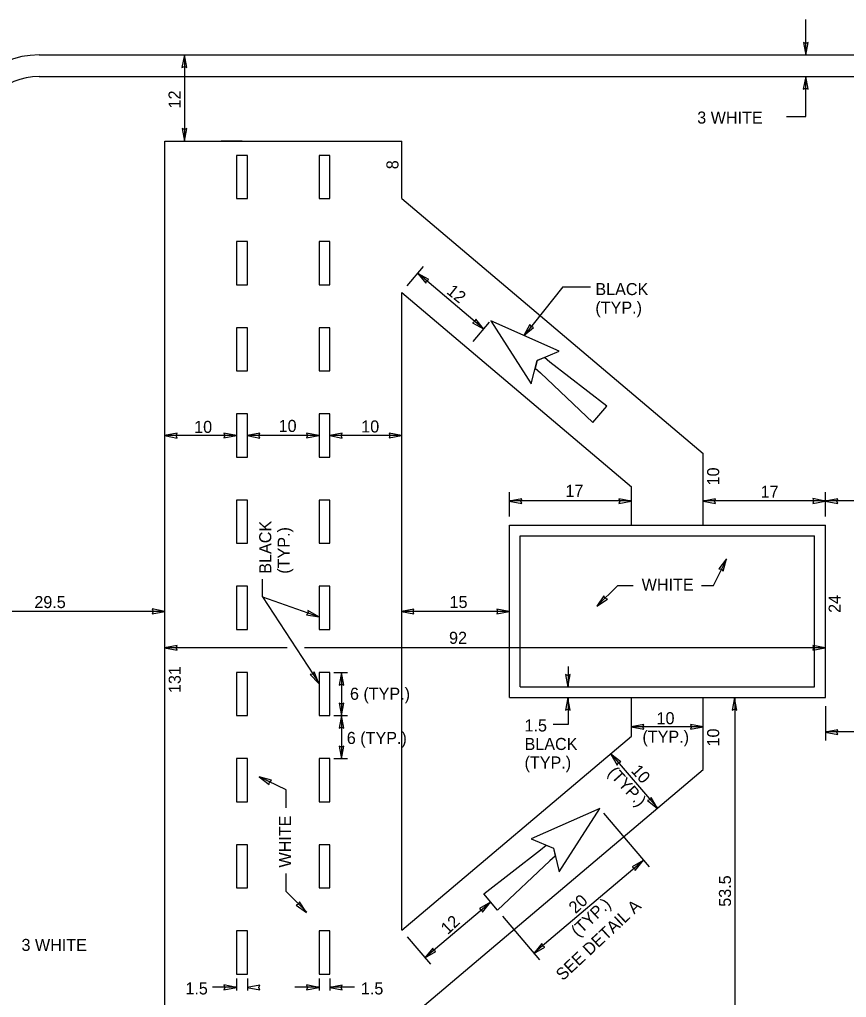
# Model space of a CAD drawing. Extents: x 319706 to 320019, y 1621790 to 1621996.
# Drawn here: x 319813.6 to 319909.6, y 1621877.2 to 1621990.6 of the extents above; entities that cross this region are included whole.
import ezdxf

# ---------------------------------------------------------------- set-up
doc = ezdxf.new("R2010")
doc.units = 0
for name, color, linetype in [('1', 7, 'Continuous'), ('40', 7, 'Continuous'), ('48', 7, 'Continuous'), ('52', 7, 'Continuous')]:
    doc.layers.add(name, color=color, linetype=linetype)

msp = doc.modelspace()

# ---------------------------------------------------------------- linework, layer by layer
at = {"layer": '1'}
for p, q in [((319815.88, 1621986.54), (319975.88, 1621986.54)), ((319815.88, 1621984.04), (319975.88, 1621984.04)), ((319830.47, 1621976.54), (319857.96, 1621976.54)), ((319830.47, 1621867.37), (319830.47, 1621976.54)), ((319857.96, 1621969.87), (319857.96, 1621976.54)), ((319857.96, 1621969.87), (319892.96, 1621940.29)), ((319857.96, 1621958.96), (319884.63, 1621936.42)), ((319857.96, 1621884.95), (319857.96, 1621958.96)), ((319892.96, 1621931.96), (319892.96, 1621940.29)), ((319884.63, 1621931.96), (319884.63, 1621936.42)), ((319870.46, 1621931.96), (319907.13, 1621931.96)), ((319870.46, 1621911.96), (319870.46, 1621931.96)), ((319907.13, 1621911.96), (319907.13, 1621931.96)), ((319871.71, 1621930.71), (319905.88, 1621930.71)), ((319871.71, 1621913.21), (319871.71, 1621930.71)), ((319905.88, 1621913.21), (319905.88, 1621930.71)), ((319871.71, 1621913.21), (319905.88, 1621913.21)), ((319870.46, 1621911.96), (319907.13, 1621911.96)), ((319884.63, 1621907.49), (319884.63, 1621911.96)), ((319892.96, 1621903.62), (319892.96, 1621911.96)), ((319857.96, 1621884.95), (319884.63, 1621907.49)), ((319857.96, 1621874.04), (319892.96, 1621903.62))]:
    msp.add_line(p, q, dxfattribs=at)
for radius in [10, 7.5]:
    msp.add_arc((319815.88, 1621976.54), radius, 90, 180, dxfattribs=at)
at = {"layer": '40'}
for p, q in [((319840.05, 1621974.87), (319838.8, 1621974.87)), ((319838.8, 1621974.87), (319838.8, 1621969.87)), ((319840.05, 1621969.87), (319840.05, 1621974.87)), ((319849.63, 1621974.87), (319848.38, 1621974.87)), ((319848.38, 1621974.87), (319848.38, 1621969.87)), ((319849.63, 1621969.87), (319849.63, 1621974.87)), ((319838.8, 1621969.87), (319840.05, 1621969.87)), ((319848.38, 1621969.87), (319849.63, 1621969.87)), ((319840.05, 1621964.87), (319838.8, 1621964.87)), ((319838.8, 1621964.87), (319838.8, 1621959.87)), ((319840.05, 1621959.87), (319840.05, 1621964.87)), ((319849.63, 1621964.87), (319848.38, 1621964.87)), ((319848.38, 1621964.87), (319848.38, 1621959.87)), ((319849.63, 1621959.87), (319849.63, 1621964.87)), ((319838.8, 1621959.87), (319840.05, 1621959.87)), ((319848.38, 1621959.87), (319849.63, 1621959.87)), ((319868.29, 1621955.69), (319872.99, 1621948.37)), ((319876.24, 1621952.17), (319868.29, 1621955.69)), ((319840.05, 1621954.87), (319838.8, 1621954.87)), ((319838.8, 1621954.87), (319838.8, 1621949.87)), ((319840.05, 1621949.87), (319840.05, 1621954.87)), ((319849.63, 1621954.87), (319848.38, 1621954.87)), ((319848.38, 1621954.87), (319848.38, 1621949.87)), ((319849.63, 1621949.87), (319849.63, 1621954.87)), ((319873.67, 1621951.08), (319876.24, 1621952.17)), ((319872.99, 1621948.37), (319873.67, 1621951.08)), ((319873.67, 1621951.08), (319873.44, 1621950.18)), ((319874.53, 1621951.44), (319873.67, 1621951.08)), ((319875.16, 1621950.9), (319874.53, 1621951.44)), ((319881.76, 1621945.79), (319875.16, 1621950.9)), ((319838.8, 1621949.87), (319840.05, 1621949.87)), ((319848.38, 1621949.87), (319849.63, 1621949.87)), ((319873.44, 1621950.18), (319874.07, 1621949.63)), ((319874.07, 1621949.63), (319880.13, 1621943.89)), ((319840.05, 1621944.87), (319838.8, 1621944.87)), ((319838.8, 1621944.87), (319838.8, 1621939.87)), ((319840.05, 1621939.87), (319840.05, 1621944.87)), ((319849.63, 1621944.87), (319848.38, 1621944.87)), ((319848.38, 1621944.87), (319848.38, 1621939.87)), ((319849.63, 1621939.87), (319849.63, 1621944.87)), ((319880.13, 1621943.89), (319881.76, 1621945.79)), ((319838.8, 1621939.87), (319840.05, 1621939.87)), ((319848.38, 1621939.87), (319849.63, 1621939.87)), ((319840.05, 1621934.87), (319838.8, 1621934.87)), ((319838.8, 1621934.87), (319838.8, 1621929.87)), ((319840.05, 1621929.87), (319840.05, 1621934.87)), ((319849.63, 1621934.87), (319848.38, 1621934.87)), ((319848.38, 1621934.87), (319848.38, 1621929.87)), ((319849.63, 1621929.87), (319849.63, 1621934.87)), ((319838.8, 1621929.87), (319840.05, 1621929.87)), ((319848.38, 1621929.87), (319849.63, 1621929.87)), ((319840.05, 1621924.87), (319838.8, 1621924.87)), ((319838.8, 1621924.87), (319838.8, 1621919.87)), ((319840.05, 1621919.87), (319840.05, 1621924.87)), ((319849.63, 1621924.87), (319848.38, 1621924.87)), ((319848.38, 1621924.87), (319848.38, 1621919.87)), ((319849.63, 1621919.87), (319849.63, 1621924.87)), ((319838.8, 1621919.87), (319840.05, 1621919.87)), ((319848.38, 1621919.87), (319849.63, 1621919.87)), ((319840.05, 1621914.87), (319838.8, 1621914.87)), ((319838.8, 1621914.87), (319838.8, 1621909.87)), ((319840.05, 1621909.87), (319840.05, 1621914.87)), ((319849.63, 1621914.87), (319848.38, 1621914.87)), ((319848.38, 1621914.87), (319848.38, 1621909.87)), ((319849.63, 1621909.87), (319849.63, 1621914.87)), ((319838.8, 1621909.87), (319840.05, 1621909.87)), ((319848.38, 1621909.87), (319849.63, 1621909.87)), ((319840.05, 1621904.87), (319838.8, 1621904.87)), ((319838.8, 1621904.87), (319838.8, 1621899.87)), ((319840.05, 1621899.87), (319840.05, 1621904.87)), ((319849.63, 1621904.87), (319848.38, 1621904.87)), ((319848.38, 1621904.87), (319848.38, 1621899.87)), ((319849.63, 1621899.87), (319849.63, 1621904.87)), ((319838.8, 1621899.87), (319840.05, 1621899.87)), ((319848.38, 1621899.87), (319849.63, 1621899.87)), ((319880.94, 1621899.07), (319872.99, 1621895.55)), ((319876.24, 1621891.75), (319880.94, 1621899.07)), ((319840.05, 1621894.87), (319838.8, 1621894.87)), ((319838.8, 1621894.87), (319838.8, 1621889.87)), ((319840.05, 1621889.87), (319840.05, 1621894.87)), ((319849.63, 1621894.87), (319848.38, 1621894.87)), ((319848.38, 1621894.87), (319848.38, 1621889.87)), ((319849.63, 1621889.87), (319849.63, 1621894.87)), ((319872.99, 1621895.55), (319875.57, 1621894.46)), ((319867.48, 1621889.17), (319874.07, 1621894.28)), ((319874.07, 1621894.28), (319874.71, 1621894.82)), ((319874.71, 1621894.82), (319875.57, 1621894.46)), ((319875.57, 1621894.46), (319875.79, 1621893.56)), ((319875.57, 1621894.46), (319876.24, 1621891.75)), ((319875.16, 1621893.02), (319869.1, 1621887.28)), ((319875.79, 1621893.56), (319875.16, 1621893.02)), ((319838.8, 1621889.87), (319840.05, 1621889.87)), ((319848.38, 1621889.87), (319849.63, 1621889.87)), ((319869.1, 1621887.28), (319867.48, 1621889.17)), ((319840.05, 1621884.87), (319838.8, 1621884.87)), ((319838.8, 1621884.87), (319838.8, 1621879.87)), ((319840.05, 1621879.87), (319840.05, 1621884.87)), ((319849.63, 1621884.87), (319848.38, 1621884.87)), ((319848.38, 1621884.87), (319848.38, 1621879.87)), ((319849.63, 1621879.87), (319849.63, 1621884.87)), ((319838.8, 1621879.87), (319840.05, 1621879.87)), ((319848.38, 1621879.87), (319849.63, 1621879.87))]:
    msp.add_line(p, q, dxfattribs=at)
at = {"layer": '48'}
for p, q in [((319904.87, 1621986.54), (319904.87, 1621990.64)), ((319832.74, 1621986.54), (319832.74, 1621976.54)), ((319904.87, 1621979.38), (319904.87, 1621984.04)), ((319902.62, 1621979.38), (319904.87, 1621979.38)), ((319839.43, 1621976.54), (319837.02, 1621976.54)), ((319858.61, 1621959.73), (319860.5, 1621961.97)), ((319859.86, 1621961.21), (319867.5, 1621954.75)), ((319876.65, 1621959.64), (319872.16, 1621953.98)), ((319876.65, 1621959.64), (319879.86, 1621959.64)), ((319866.25, 1621953.27), (319868.14, 1621955.52)), ((319838.8, 1621942.37), (319830.47, 1621942.37)), ((319848.38, 1621942.37), (319840.05, 1621942.37)), ((319857.96, 1621942.37), (319849.63, 1621942.37)), ((319870.46, 1621932.97), (319870.46, 1621935.78)), ((319907.13, 1621932.97), (319907.13, 1621935.78)), ((319884.63, 1621934.78), (319870.46, 1621934.78)), ((319907.13, 1621934.78), (319892.96, 1621934.78)), ((319919.63, 1621934.78), (319907.13, 1621934.78)), ((319894.16, 1621924.96), (319895.7, 1621928.07)), ((319841.8, 1621923.64), (319841.8, 1621925.71)), ((319883.04, 1621924.96), (319880.62, 1621922.57)), ((319883.04, 1621924.96), (319884.83, 1621924.96)), ((319892.74, 1621924.96), (319894.16, 1621924.96)), ((319841.8, 1621923.64), (319848.38, 1621921.33)), ((319841.8, 1621923.64), (319848.38, 1621913.58)), ((319830.47, 1621921.96), (319805.88, 1621921.96)), ((319870.46, 1621921.96), (319857.96, 1621921.96)), ((319844.66, 1621917.74), (319830.47, 1621917.74)), ((319907.13, 1621917.74), (319846.69, 1621917.74)), ((319877.27, 1621915.58), (319877.27, 1621913.21)), ((319850.09, 1621914.87), (319851.66, 1621914.87)), ((319850.99, 1621914.87), (319850.99, 1621909.87)), ((319877.27, 1621911.96), (319877.27, 1621908.84)), ((319896.62, 1621911.96), (319896.62, 1621867.37)), ((319907.13, 1621910.96), (319907.13, 1621906.98)), ((319850.09, 1621909.87), (319851.66, 1621909.87)), ((319850.99, 1621909.87), (319850.99, 1621904.87)), ((319877.27, 1621908.84), (319875.54, 1621908.84)), ((319884.63, 1621908.59), (319892.96, 1621908.59)), ((319919.63, 1621907.98), (319907.13, 1621907.98)), ((319882.25, 1621905.42), (319887.67, 1621899.09)), ((319850.09, 1621904.87), (319851.66, 1621904.87)), ((319844.55, 1621901.23), (319841.44, 1621902.77)), ((319844.55, 1621899.16), (319844.55, 1621901.23)), ((319881.4, 1621898.53), (319886.67, 1621892.3)), ((319886.03, 1621893.06), (319873.31, 1621882.29)), ((319844.55, 1621889.46), (319844.55, 1621891.53)), ((319844.55, 1621889.46), (319846.95, 1621887.04)), ((319868.29, 1621888.23), (319860.66, 1621881.76)), ((319869.68, 1621886.58), (319873.95, 1621881.52)), ((319858.61, 1621884.19), (319861.3, 1621881)), ((319838.8, 1621879.37), (319838.8, 1621877.96)), ((319840.05, 1621879.37), (319840.05, 1621877.96)), ((319848.38, 1621879.37), (319848.38, 1621877.96)), ((319849.63, 1621879.37), (319849.63, 1621877.96)), ((319838.8, 1621878.33), (319835.99, 1621878.33)), ((319848.38, 1621878.33), (319845.57, 1621878.33)), ((319852.5, 1621878.33), (319849.63, 1621878.33))]:
    msp.add_line(p, q, dxfattribs=at)
at = {"layer": '52'}
for p, q in [((319904.85, 1621987.86), (319904.58, 1621987.97)), ((319904.58, 1621987.97), (319904.85, 1621986.52)), ((319904.85, 1621986.52), (319905.13, 1621987.97)), ((319905.13, 1621987.97), (319904.85, 1621987.86)), ((319832.74, 1621986.54), (319832.46, 1621985.09)), ((319833.01, 1621985.09), (319832.74, 1621986.54)), ((319832.46, 1621985.09), (319832.74, 1621985.2)), ((319832.74, 1621985.2), (319833.01, 1621985.09)), ((319904.85, 1621984.02), (319904.57, 1621982.57)), ((319905.12, 1621982.57), (319904.85, 1621984.02)), ((319904.57, 1621982.57), (319904.85, 1621982.68)), ((319904.85, 1621982.68), (319905.12, 1621982.57)), ((319832.74, 1621977.88), (319832.47, 1621977.99)), ((319832.47, 1621977.99), (319832.74, 1621976.54)), ((319832.74, 1621976.54), (319833.02, 1621977.99)), ((319833.02, 1621977.99), (319832.74, 1621977.88)), ((319859.84, 1621961.19), (319860.76, 1621960.04)), ((319861.12, 1621960.46), (319859.84, 1621961.19)), ((319860.76, 1621960.04), (319860.86, 1621960.32)), ((319860.86, 1621960.32), (319861.12, 1621960.46)), ((319866.45, 1621955.6), (319866.19, 1621955.46)), ((319866.19, 1621955.46), (319867.47, 1621954.73)), ((319866.55, 1621955.88), (319866.45, 1621955.6)), ((319867.47, 1621954.73), (319866.55, 1621955.88)), ((319872.82, 1621955.26), (319872.14, 1621953.96)), ((319872.97, 1621955.01), (319872.82, 1621955.26)), ((319873.26, 1621954.92), (319872.97, 1621955.01)), ((319872.14, 1621953.96), (319873.26, 1621954.92)), ((319831.9, 1621942.63), (319830.45, 1621942.36)), ((319831.79, 1621942.36), (319831.9, 1621942.63)), ((319838.78, 1621942.36), (319837.33, 1621942.64)), ((319837.33, 1621942.64), (319837.44, 1621942.36)), ((319841.48, 1621942.63), (319840.03, 1621942.36)), ((319841.37, 1621942.36), (319841.48, 1621942.63)), ((319848.36, 1621942.36), (319846.91, 1621942.64)), ((319846.91, 1621942.64), (319847.02, 1621942.36)), ((319851.06, 1621942.63), (319849.61, 1621942.36)), ((319850.95, 1621942.36), (319851.06, 1621942.63)), ((319857.94, 1621942.36), (319856.49, 1621942.64)), ((319856.49, 1621942.64), (319856.6, 1621942.36)), ((319830.45, 1621942.36), (319831.9, 1621942.08)), ((319831.9, 1621942.08), (319831.79, 1621942.36)), ((319837.44, 1621942.36), (319837.33, 1621942.09)), ((319837.33, 1621942.09), (319838.78, 1621942.36)), ((319840.03, 1621942.36), (319841.48, 1621942.08)), ((319841.48, 1621942.08), (319841.37, 1621942.36)), ((319847.02, 1621942.36), (319846.91, 1621942.09)), ((319846.91, 1621942.09), (319848.36, 1621942.36)), ((319849.61, 1621942.36), (319851.06, 1621942.08)), ((319851.06, 1621942.08), (319850.95, 1621942.36)), ((319856.6, 1621942.36), (319856.49, 1621942.09)), ((319856.49, 1621942.09), (319857.94, 1621942.36)), ((319871.89, 1621935.03), (319870.44, 1621934.76)), ((319870.44, 1621934.76), (319871.89, 1621934.48)), ((319871.78, 1621934.76), (319871.89, 1621935.03)), ((319871.89, 1621934.48), (319871.78, 1621934.76)), ((319884.61, 1621934.75), (319883.16, 1621935.03)), ((319883.16, 1621935.03), (319883.27, 1621934.75)), ((319883.27, 1621934.75), (319883.16, 1621934.48)), ((319883.16, 1621934.48), (319884.61, 1621934.75)), ((319894.39, 1621935.02), (319892.94, 1621934.75)), ((319892.94, 1621934.75), (319894.39, 1621934.47)), ((319894.28, 1621934.75), (319894.39, 1621935.02)), ((319894.39, 1621934.47), (319894.28, 1621934.75)), ((319907.11, 1621934.76), (319905.66, 1621935.04)), ((319905.66, 1621935.04), (319905.77, 1621934.76)), ((319905.77, 1621934.76), (319905.66, 1621934.49)), ((319905.66, 1621934.49), (319907.11, 1621934.76)), ((319908.56, 1621935.03), (319907.11, 1621934.76)), ((319907.11, 1621934.76), (319908.56, 1621934.48)), ((319908.45, 1621934.76), (319908.56, 1621935.03)), ((319908.56, 1621934.48), (319908.45, 1621934.76)), ((319895.67, 1621928.05), (319894.77, 1621926.88)), ((319895.27, 1621926.64), (319895.67, 1621928.05)), ((319894.77, 1621926.88), (319895.07, 1621926.85)), ((319895.07, 1621926.85), (319895.27, 1621926.64)), ((319881.44, 1621923.77), (319880.6, 1621922.55)), ((319880.6, 1621922.55), (319881.83, 1621923.37)), ((319881.55, 1621923.5), (319881.44, 1621923.77)), ((319881.83, 1621923.37), (319881.55, 1621923.5)), ((319830.47, 1621921.96), (319829.02, 1621922.24)), ((319829.02, 1621922.24), (319829.13, 1621921.96)), ((319859.39, 1621922.21), (319857.94, 1621921.94)), ((319859.28, 1621921.94), (319859.39, 1621922.21)), ((319870.44, 1621921.93), (319868.99, 1621922.21)), ((319868.99, 1621922.21), (319869.1, 1621921.93)), ((319829.13, 1621921.96), (319829.02, 1621921.69)), ((319829.02, 1621921.69), (319830.47, 1621921.96)), ((319847.09, 1621921.76), (319846.9, 1621921.54)), ((319846.9, 1621921.54), (319848.36, 1621921.32)), ((319848.36, 1621921.32), (319847.08, 1621922.06)), ((319847.08, 1621922.06), (319847.09, 1621921.76)), ((319857.94, 1621921.94), (319859.39, 1621921.66)), ((319859.39, 1621921.66), (319859.28, 1621921.94)), ((319869.1, 1621921.93), (319868.99, 1621921.66)), ((319868.99, 1621921.66), (319870.44, 1621921.93)), ((319831.9, 1621918), (319830.45, 1621917.73)), ((319830.45, 1621917.73), (319831.9, 1621917.45)), ((319831.79, 1621917.73), (319831.9, 1621918)), ((319831.9, 1621917.45), (319831.79, 1621917.73)), ((319907.11, 1621917.72), (319905.66, 1621918)), ((319905.66, 1621918), (319905.77, 1621917.72)), ((319905.77, 1621917.72), (319905.66, 1621917.45)), ((319905.66, 1621917.45), (319907.11, 1621917.72)), ((319847.63, 1621914.69), (319847.34, 1621914.64)), ((319847.34, 1621914.64), (319848.36, 1621913.57)), ((319847.8, 1621914.94), (319847.63, 1621914.69)), ((319848.36, 1621913.57), (319847.8, 1621914.94)), ((319850.98, 1621914.86), (319850.7, 1621913.41)), ((319851.25, 1621913.41), (319850.98, 1621914.86)), ((319877.25, 1621914.52), (319876.98, 1621914.63)), ((319876.98, 1621914.63), (319877.25, 1621913.18)), ((319877.25, 1621913.18), (319877.53, 1621914.63)), ((319877.53, 1621914.63), (319877.25, 1621914.52)), ((319850.7, 1621913.41), (319850.98, 1621913.52)), ((319850.98, 1621913.52), (319851.25, 1621913.41)), ((319877.25, 1621911.94), (319876.97, 1621910.49)), ((319877.52, 1621910.49), (319877.25, 1621911.94)), ((319896.59, 1621911.94), (319896.31, 1621910.49)), ((319896.86, 1621910.49), (319896.59, 1621911.94)), ((319850.98, 1621911.2), (319850.71, 1621911.31)), ((319850.71, 1621911.31), (319850.98, 1621909.86)), ((319850.98, 1621909.86), (319851.26, 1621911.31)), ((319851.26, 1621911.31), (319850.98, 1621911.2)), ((319850.98, 1621909.86), (319850.7, 1621908.41)), ((319851.25, 1621908.41), (319850.98, 1621909.86)), ((319876.97, 1621910.49), (319877.25, 1621910.6)), ((319877.25, 1621910.6), (319877.52, 1621910.49)), ((319896.31, 1621910.49), (319896.59, 1621910.6)), ((319896.59, 1621910.6), (319896.86, 1621910.49)), ((319850.7, 1621908.41), (319850.98, 1621908.52)), ((319850.98, 1621908.52), (319851.25, 1621908.41)), ((319886.06, 1621908.84), (319884.61, 1621908.57)), ((319884.61, 1621908.57), (319886.06, 1621908.29)), ((319885.95, 1621908.57), (319886.06, 1621908.84)), ((319886.06, 1621908.29), (319885.95, 1621908.57)), ((319892.94, 1621908.57), (319891.49, 1621908.85)), ((319891.49, 1621908.85), (319891.6, 1621908.57)), ((319891.6, 1621908.57), (319891.49, 1621908.3)), ((319891.49, 1621908.3), (319892.94, 1621908.57)), ((319908.56, 1621908.22), (319907.11, 1621907.95)), ((319907.11, 1621907.95), (319908.56, 1621907.67)), ((319908.45, 1621907.95), (319908.56, 1621908.22)), ((319908.56, 1621907.67), (319908.45, 1621907.95)), ((319850.98, 1621906.2), (319850.71, 1621906.31)), ((319850.71, 1621906.31), (319850.98, 1621904.86)), ((319850.98, 1621904.86), (319851.26, 1621906.31)), ((319851.26, 1621906.31), (319850.98, 1621906.2)), ((319882.23, 1621905.4), (319882.96, 1621904.12)), ((319883.38, 1621904.48), (319882.23, 1621905.4)), ((319882.96, 1621904.12), (319883.1, 1621904.38)), ((319883.1, 1621904.38), (319883.38, 1621904.48)), ((319841.43, 1621902.76), (319842.6, 1621901.86)), ((319842.84, 1621902.36), (319841.43, 1621902.76)), ((319842.6, 1621901.86), (319842.63, 1621902.16)), ((319842.63, 1621902.16), (319842.84, 1621902.36)), ((319886.78, 1621900.09), (319886.5, 1621900)), ((319886.5, 1621900), (319887.65, 1621899.07)), ((319886.92, 1621900.36), (319886.78, 1621900.09)), ((319887.65, 1621899.07), (319886.92, 1621900.36)), ((319886, 1621893.04), (319884.72, 1621892.32)), ((319885.07, 1621891.9), (319886, 1621893.04)), ((319884.72, 1621892.32), (319884.98, 1621892.17)), ((319884.98, 1621892.17), (319885.07, 1621891.9)), ((319846.11, 1621888.26), (319845.98, 1621887.98)), ((319846.93, 1621887.03), (319846.11, 1621888.26)), ((319868.27, 1621888.21), (319866.98, 1621887.48)), ((319867.33, 1621887.06), (319868.27, 1621888.21)), ((319845.98, 1621887.98), (319845.71, 1621887.87)), ((319845.71, 1621887.87), (319846.93, 1621887.03)), ((319866.98, 1621887.48), (319867.24, 1621887.34)), ((319867.24, 1621887.34), (319867.33, 1621887.06)), ((319861.57, 1621882.89), (319860.64, 1621881.74)), ((319860.64, 1621881.74), (319861.92, 1621882.47)), ((319861.66, 1621882.61), (319861.57, 1621882.89)), ((319861.92, 1621882.47), (319861.66, 1621882.61)), ((319874.22, 1621883.41), (319873.29, 1621882.27)), ((319873.29, 1621882.27), (319874.57, 1621882.99)), ((319874.31, 1621883.13), (319874.22, 1621883.41)), ((319874.57, 1621882.99), (319874.31, 1621883.13)), ((319838.78, 1621878.32), (319837.33, 1621878.6)), ((319837.33, 1621878.6), (319837.44, 1621878.32)), ((319837.44, 1621878.32), (319837.33, 1621878.05)), ((319837.33, 1621878.05), (319838.78, 1621878.32)), ((319841.48, 1621878.59), (319840.03, 1621878.32)), ((319840.03, 1621878.32), (319841.48, 1621878.04)), ((319841.37, 1621878.32), (319841.48, 1621878.59)), ((319841.48, 1621878.04), (319841.37, 1621878.32)), ((319848.36, 1621878.32), (319846.91, 1621878.6)), ((319846.91, 1621878.6), (319847.02, 1621878.32)), ((319847.02, 1621878.32), (319846.91, 1621878.05)), ((319846.91, 1621878.05), (319848.36, 1621878.32)), ((319851.06, 1621878.59), (319849.61, 1621878.32)), ((319849.61, 1621878.32), (319851.06, 1621878.04)), ((319850.95, 1621878.32), (319851.06, 1621878.59)), ((319851.06, 1621878.04), (319850.95, 1621878.32))]:
    msp.add_line(p, q, dxfattribs=at)

# ---------------------------------------------------------------- texts
at = {"layer": '48'}
for s, rotation, p in [('12', 90, (319832.3, 1621980.33)), ('8', 90, (319857.59, 1621973.27)), ('12', 321.237, (319863.07, 1621958.93)), ('10', 90, (319894.81, 1621936.58)), ('BLACK', 90, (319842.83, 1621926.33)), ('(TYP.)', 90, (319844.98, 1621926.33)), ('24', 90, (319908.91, 1621921.78)), ('131', 90, (319832.32, 1621912.48)), ('10', 90, (319894.81, 1621906.28)), ('10', 312.4213, (319884.5, 1621903.4)), ('(TYP.)', 312.4213, (319881.8, 1621903.17)), ('WHITE', 90, (319845.13, 1621892.23)), ('53.5', 90, (319896.18, 1621887.68)), ('SEE DETAIL A', 43.0352, (319876.66, 1621879.02)), ('20', 43.0352, (319878.14, 1621886.8)), ('(TYP.)', 43.0352, (319878.41, 1621884.11)), ('12', 43.0352, (319863.3, 1621884.38))]:
    msp.add_text(s, height=1.4, rotation=rotation, dxfattribs=at).set_placement(p)
for s, p in [('3 WHITE', (319892.26, 1621978.57)), ('BLACK', (319880.44, 1621958.66)), ('(TYP.)', (319880.44, 1621956.51)), ('10', (319833.88, 1621942.67)), ('10', (319843.68, 1621942.78)), ('10', (319853.27, 1621942.72)), ('17', (319876.96, 1621935.25)), ('17', (319899.62, 1621935.14)), ('WHITE', (319885.81, 1621924.37)), ('29.5', (319815.33, 1621922.34)), ('15', (319863.52, 1621922.35)), ('92', (319863.46, 1621918.19)), ('6 (TYP.)', (319851.96, 1621911.7)), ('10', (319887.54, 1621908.86)), ('1.5', (319872.22, 1621908.02)), ('6 (TYP.)', (319851.59, 1621906.57)), ('(TYP.)', (319885.9, 1621906.71)), ('BLACK', (319872.22, 1621905.87)), ('(TYP.)', (319872.22, 1621903.72)), ('3 WHITE', (319813.84, 1621882.55)), ('1.5', (319832.86, 1621877.5)), ('1.5', (319853.23, 1621877.5))]:
    msp.add_text(s, height=1.4, dxfattribs=at).set_placement(p)

doc.saveas('drawing.dxf')
